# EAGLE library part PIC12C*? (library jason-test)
MICROCONTROLLER
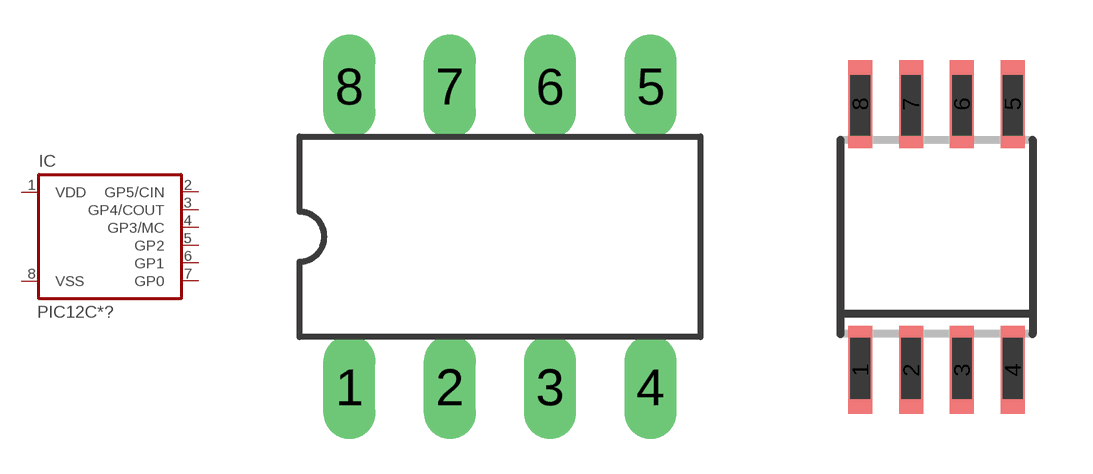
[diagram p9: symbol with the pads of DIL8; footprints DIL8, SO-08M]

Designator prefix IC

## PIC12C508P, PIC12C509P, PIC12C671P, PIC12C672P  [DIL8]
1  VDD  pwr
2  GP5/CIN
3  GP4/COUT
4  GP3/MC  in
5  GP2
6  GP1
7  GP0
8  VSS  pwr

## PIC12C508JN, PIC12C509JN, PIC12C671JN, PIC12C672JN  [DIL8]
Pads as for DIL8

## PIC12C508SM, PIC12C509SM, PIC12C671SM, PIC12C672SM  [SO-08M]
Pads as for DIL8

## PIC12C629SN  [SO-08]
Pads as for DIL8

## Footprint DIL8 (pad centres in mm)
Dual In Line package type P
drill 0.813 long: 1 -3.81,-3.81; 2 -1.27,-3.81; 3 1.27,-3.81; 4 3.81,-3.81; 5 3.81,3.81; 6 1.27,3.81; 7 -1.27,3.81; 8 -3.81,3.81

## Footprint SO-08M (pad centres in mm)
Small Outline Medium Plastic Gull Wing 207-mil body, package type SM
smd 0.6 x 2.2: 1 -1.905,-3.33; 2 -0.635,-3.33; 3 0.635,-3.33; 4 1.905,-3.33; 5 1.905,3.33; 6 0.635,3.33; 7 -0.635,3.33; 8 -1.905,3.33

## Footprint SO-08 (pad centres in mm)
Small Outline Narrow Plastic Gull Wing 150-mil body, package type SN
smd 0.6 x 2.2: 1 -1.905,-2.6; 2 -0.635,-2.6; 3 0.635,-2.6; 4 1.905,-2.6; 5 1.905,2.6; 6 0.635,2.6; 7 -0.635,2.6; 8 -1.905,2.6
